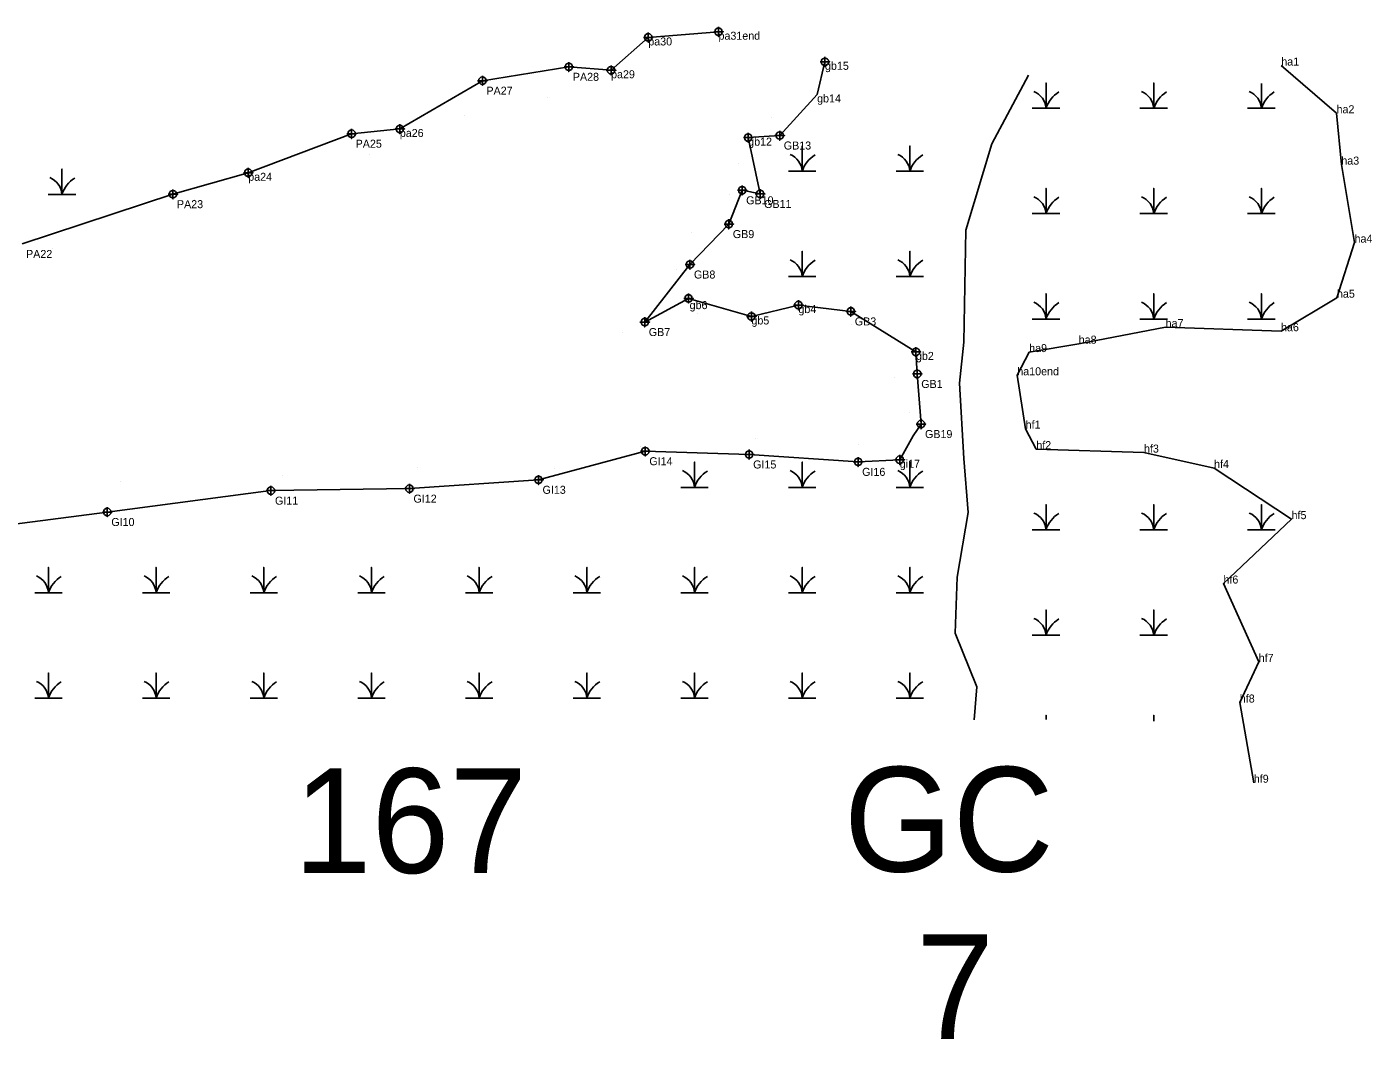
# Model space of a CAD drawing. Extents: x 2072529 to 2268796, y 436423 to 470397.
# Drawn here: x 2186918 to 2187758, y 453120 to 453752 of the extents above; entities that cross this region are included whole.
import ezdxf

# ---------------------------------------------------------------- set-up
doc = ezdxf.new("R2010")
doc.units = 0
for name, color, linetype in [('Default', 7, 'Continuous'), ('Exist Environmental Wetland Boundary', 7, 'Continuous'), ('Exist Environmental Wetland Boundary Cogo Comment', 7, 'Continuous'), ('Exist Environmental Wetland Boundary Cogo Point CELL', 7, 'Continuous'), ('Exist Hydro Jurisdictional Stream or Body of Water NEU Mitigable', 7, 'Continuous'), ('Exist Hydro Swamp or Marsh', 7, 'Continuous')]:
    doc.layers.add(name, color=color, linetype=linetype)

msp = doc.modelspace()

# ---------------------------------------------------------------- linework, layer by layer
at = {"layer": 'Exist Environmental Wetland Boundary'}
for points in [[(2186914.68, 453616.56), (2187008.89, 453647.61), (2187055.94, 453660.98), (2187120.52, 453685.38), (2187150.61, 453688.32), (2187202.21, 453718.49), (2187256.17, 453727.15), (2187282.56, 453725), (2187305.8, 453745.49), (2187349.64, 453749.06)], [(2187476.13, 453504.11), (2187473.78, 453535.38), (2187472.97, 453549.14), (2187432.29, 453574.42), (2187399.56, 453578.39), (2187370.22, 453571.28), (2187330.92, 453582.59), (2187303.63, 453567.79), (2187331.81, 453603.71), (2187356.1, 453628.96), (2187364.42, 453650.04), (2187375.61, 453647.76), (2187368.19, 453682.93), (2187387.95, 453684.27), (2187411.24, 453709.91), (2187416.15, 453730.28)], [(2187701.15, 453727.92), (2187735.66, 453698.15), (2187738.65, 453666.09), (2187746.9, 453617.39), (2187735.92, 453583), (2187700.97, 453562.06), (2187628.91, 453564.59), (2187574.63, 453554.29), (2187543.69, 453549.04), (2187536.26, 453534.55), (2187541.47, 453501.21)], [(2186590.17, 453193.44), (2186576.37, 453212.42), (2186571.99, 453259.45), (2186574.44, 453309.06), (2186581.86, 453375.55), (2186597.55, 453411.45), (2186689.52, 453421.44), (2186746.86, 453423.8), (2186843.7, 453432.98), (2186967.92, 453449.19), (2187070.14, 453462.52), (2187156.63, 453463.76), (2187237.25, 453469.29), (2187303.93, 453487.14), (2187368.79, 453485.11), (2187436.86, 453480.5), (2187462.85, 453481.82), (2187471.15, 453496.67), (2187476.13, 453504.11)], [(2187541.47, 453501.21), (2187548.15, 453488.43), (2187615.39, 453486.28), (2187659.17, 453476.66), (2187707.57, 453444.73), (2187665.02, 453404.52), (2187687.06, 453355.6), (2187675.24, 453330.23), (2187683.99, 453280.14)]]:
    msp.add_lwpolyline(points, dxfattribs=at)
at = {"layer": 'Exist Environmental Wetland Boundary Cogo Point CELL'}
for p, q in [((2187305.8, 453745.49), (2187305.8, 453745.49)), ((2187349.64, 453749.06), (2187349.64, 453749.06)), ((2187416.15, 453730.28), (2187416.15, 453730.28)), ((2187701.15, 453727.92), (2187701.15, 453727.92)), ((2187282.56, 453725), (2187282.56, 453725)), ((2187411.24, 453709.91), (2187411.24, 453709.91)), ((2187242.75, 453708.29), (2187242.75, 453708.29)), ((2187190.78, 453696.74), (2187190.78, 453696.74)), ((2187382.85, 453695.75), (2187382.85, 453695.75)), ((2187735.66, 453698.15), (2187735.66, 453698.15)), ((2187150.61, 453688.32), (2187150.61, 453688.32)), ((2187368.19, 453682.93), (2187368.19, 453682.93)), ((2187131.67, 453672.34), (2187131.67, 453672.34)), ((2187055.94, 453660.98), (2187055.94, 453660.98)), ((2187362.14, 453666.49), (2187362.14, 453666.49)), ((2187738.65, 453666.09), (2187738.65, 453666.09)), ((2187022.2, 453644.42), (2187022.2, 453644.42)), ((2187356.65, 453647.29), (2187356.65, 453647.29)), ((2187332.48, 453623.94), (2187332.48, 453623.94)), ((2187746.9, 453617.39), (2187746.9, 453617.39)), ((2186933.88, 453613.88), (2186933.88, 453613.88)), ((2187323.38, 453600.64), (2187323.38, 453600.64)), ((2187399.56, 453578.39), (2187399.56, 453578.39)), ((2187735.92, 453583), (2187735.92, 453583)), ((2187336.61, 453573.27), (2187336.61, 453573.27)), ((2187370.22, 453571.28), (2187370.22, 453571.28)), ((2187289.47, 453561.32), (2187289.47, 453561.32)), ((2187432.56, 453566.23), (2187432.56, 453566.23)), ((2187628.91, 453564.59), (2187628.91, 453564.59)), ((2187700.97, 453562.06), (2187700.97, 453562.06)), ((2187574.63, 453554.29), (2187574.63, 453554.29)), ((2187472.97, 453549.14), (2187472.97, 453549.14)), ((2187543.69, 453549.04), (2187543.69, 453549.04)), ((2187536.26, 453534.55), (2187536.26, 453534.55)), ((2187459.49, 453533.03), (2187459.49, 453533.03)), ((2187468.82, 453511.58), (2187468.82, 453511.58)), ((2187541.47, 453501.21), (2187541.47, 453501.21)), ((2187372.89, 453494.83), (2187372.89, 453494.83)), ((2187471.15, 453496.67), (2187471.15, 453496.67)), ((2187471.15, 453496.67), (2187471.15, 453496.67)), ((2187301.03, 453490.02), (2187301.03, 453490.02)), ((2187437.13, 453491.21), (2187437.13, 453491.21)), ((2187548.15, 453488.43), (2187548.15, 453488.43)), ((2187615.39, 453486.28), (2187615.39, 453486.28)), ((2187161.36, 453477.08), (2187161.36, 453477.08)), ((2187247.26, 453476.05), (2187247.26, 453476.05)), ((2187462.85, 453481.82), (2187462.85, 453481.82)), ((2187659.17, 453476.66), (2187659.17, 453476.66)), ((2186976.12, 453468.4), (2186976.12, 453468.4)), ((2187077.3, 453472.28), (2187077.3, 453472.28)), ((2187707.57, 453444.73), (2187707.57, 453444.73)), ((2187665.02, 453404.52), (2187665.02, 453404.52)), ((2187687.06, 453355.6), (2187687.06, 453355.6)), ((2187675.24, 453330.23), (2187675.24, 453330.23)), ((2187683.99, 453280.14), (2187683.99, 453280.14))]:
    msp.add_line(p, q, dxfattribs=at)
for points in [[(2187349.64, 453752.06), (2187349.64, 453746.06), (2187349.64, 453749.06), (2187352.64, 453749.06), (2187346.64, 453749.06)], [(2187305.8, 453748.49), (2187305.8, 453742.49), (2187305.8, 453745.49), (2187308.8, 453745.49), (2187302.8, 453745.49)], [(2187256.17, 453730.15), (2187256.17, 453724.15), (2187256.17, 453727.15), (2187259.17, 453727.15), (2187253.17, 453727.15)], [(2187282.56, 453728), (2187282.56, 453722), (2187282.56, 453725), (2187285.56, 453725), (2187279.56, 453725)], [(2187416.15, 453733.28), (2187416.15, 453727.28), (2187416.15, 453730.28), (2187419.15, 453730.28), (2187413.15, 453730.28)], [(2187202.21, 453721.49), (2187202.21, 453715.49), (2187202.21, 453718.49), (2187205.21, 453718.49), (2187199.21, 453718.49)], [(2187120.52, 453688.38), (2187120.52, 453682.38), (2187120.52, 453685.38), (2187123.52, 453685.38), (2187117.52, 453685.38)], [(2187150.61, 453691.32), (2187150.61, 453685.32), (2187150.61, 453688.32), (2187153.61, 453688.32), (2187147.61, 453688.32)], [(2187368.19, 453685.93), (2187368.19, 453679.93), (2187368.19, 453682.93), (2187371.19, 453682.93), (2187365.19, 453682.93)], [(2187387.92, 453687.25), (2187387.92, 453681.25), (2187387.92, 453684.25), (2187390.92, 453684.25), (2187384.92, 453684.25)], [(2187055.94, 453663.98), (2187055.94, 453657.98), (2187055.94, 453660.98), (2187058.94, 453660.98), (2187052.94, 453660.98)], [(2187364.43, 453653.05), (2187364.43, 453647.05), (2187364.43, 453650.05), (2187367.43, 453650.05), (2187361.43, 453650.05)], [(2187008.9, 453650.63), (2187008.9, 453644.63), (2187008.9, 453647.63), (2187011.9, 453647.63), (2187005.9, 453647.63)], [(2187375.61, 453650.76), (2187375.61, 453644.76), (2187375.61, 453647.76), (2187378.61, 453647.76), (2187372.61, 453647.76)], [(2187356.1, 453631.96), (2187356.1, 453625.96), (2187356.1, 453628.96), (2187359.1, 453628.96), (2187353.1, 453628.96)], [(2187331.81, 453606.71), (2187331.81, 453600.71), (2187331.81, 453603.71), (2187334.81, 453603.71), (2187328.81, 453603.71)], [(2187330.92, 453585.58), (2187330.92, 453579.58), (2187330.92, 453582.58), (2187333.92, 453582.58), (2187327.92, 453582.58)], [(2187399.56, 453581.39), (2187399.56, 453575.39), (2187399.56, 453578.39), (2187402.56, 453578.39), (2187396.56, 453578.39)], [(2187432.29, 453577.42), (2187432.29, 453571.42), (2187432.29, 453574.42), (2187435.29, 453574.42), (2187429.29, 453574.42)], [(2187303.62, 453570.79), (2187303.62, 453564.79), (2187303.62, 453567.79), (2187306.62, 453567.79), (2187300.62, 453567.79)], [(2187370.22, 453574.28), (2187370.22, 453568.28), (2187370.22, 453571.28), (2187373.22, 453571.28), (2187367.22, 453571.28)], [(2187472.98, 453552.11), (2187472.98, 453546.11), (2187472.98, 453549.11), (2187475.98, 453549.11), (2187469.98, 453549.11)], [(2187473.78, 453538.38), (2187473.78, 453532.38), (2187473.78, 453535.38), (2187476.78, 453535.38), (2187470.78, 453535.38)], [(2187476.13, 453507.11), (2187476.13, 453501.11), (2187476.13, 453504.11), (2187479.13, 453504.11), (2187473.13, 453504.11)], [(2187303.93, 453490.14), (2187303.93, 453484.14), (2187303.93, 453487.14), (2187306.93, 453487.14), (2187300.93, 453487.14)], [(2187368.79, 453488.11), (2187368.79, 453482.11), (2187368.79, 453485.11), (2187371.79, 453485.11), (2187365.79, 453485.11)], [(2187436.86, 453483.5), (2187436.86, 453477.5), (2187436.86, 453480.5), (2187439.86, 453480.5), (2187433.86, 453480.5)], [(2187462.85, 453484.82), (2187462.85, 453478.82), (2187462.85, 453481.82), (2187465.85, 453481.82), (2187459.85, 453481.82)], [(2187156.63, 453466.76), (2187156.63, 453460.76), (2187156.63, 453463.76), (2187159.63, 453463.76), (2187153.63, 453463.76)], [(2187237.25, 453472.29), (2187237.25, 453466.29), (2187237.25, 453469.29), (2187240.25, 453469.29), (2187234.25, 453469.29)], [(2187070.14, 453465.52), (2187070.14, 453459.52), (2187070.14, 453462.52), (2187073.14, 453462.52), (2187067.14, 453462.52)], [(2186967.92, 453452.19), (2186967.92, 453446.19), (2186967.92, 453449.19), (2186970.92, 453449.19), (2186964.92, 453449.19)]]:
    msp.add_lwpolyline(points, dxfattribs=at)
for centre in [(2187305.8, 453745.49), (2187349.64, 453749.06), (2187256.17, 453727.15), (2187282.56, 453725), (2187416.15, 453730.28), (2187202.21, 453718.49), (2187120.52, 453685.38), (2187150.61, 453688.32), (2187368.19, 453682.93), (2187387.92, 453684.25), (2187055.94, 453660.98), (2187364.43, 453650.05), (2187008.9, 453647.63), (2187375.61, 453647.76), (2187356.1, 453628.96), (2187331.81, 453603.71), (2187330.92, 453582.58), (2187399.56, 453578.39), (2187432.29, 453574.42), (2187303.62, 453567.79), (2187370.22, 453571.28), (2187472.98, 453549.11), (2187473.78, 453535.38), (2187476.13, 453504.11), (2187303.93, 453487.14), (2187368.79, 453485.11), (2187436.86, 453480.5), (2187462.85, 453481.82), (2187156.63, 453463.76), (2187237.25, 453469.29), (2187070.14, 453462.52), (2186967.92, 453449.19)]:
    msp.add_circle(centre, 2.34, dxfattribs=at)
at = {"layer": 'Exist Hydro Jurisdictional Stream or Body of Water NEU Mitigable'}
msp.add_lwpolyline([(2187543.28, 453721.89), (2187520.32, 453678.99), (2187504.18, 453625.18), (2187502.84, 453555.22), (2187500.15, 453529.65), (2187502.84, 453482.56), (2187505.53, 453448.93), (2187498.81, 453408.57), (2187497.46, 453373.59), (2187510.91, 453339.95), (2187509.43, 453319.33)], dxfattribs=at)
at = {"layer": 'Exist Hydro Swamp or Marsh'}
for points in [[(2187545.62, 453701.28), (2187554.22, 453701.28), (2187554.22, 453717.06), (2187554.22, 453701.28), (2187562.82, 453701.28)], [(2187612.87, 453701.28), (2187621.47, 453701.28), (2187621.47, 453717.06), (2187621.47, 453701.28), (2187630.07, 453701.28)], [(2187680.12, 453701.28), (2187688.72, 453701.28), (2187688.72, 453716.73)], [(2187688.72, 453716.73), (2187688.72, 453701.28), (2187697.32, 453701.28)], [(2187393.32, 453661.97), (2187401.92, 453661.97), (2187401.92, 453677.75), (2187401.92, 453661.97), (2187410.52, 453661.97)], [(2187460.57, 453661.97), (2187469.17, 453661.97), (2187469.17, 453677.75), (2187469.17, 453661.97), (2187477.77, 453661.97)], [(2186930.98, 453647.47), (2186939.58, 453647.47), (2186939.58, 453663.25), (2186939.58, 453647.47), (2186948.19, 453647.47)], [(2187545.62, 453635.48), (2187554.22, 453635.48), (2187554.22, 453651.26), (2187554.22, 453635.48), (2187562.82, 453635.48)], [(2187612.87, 453635.48), (2187621.47, 453635.48), (2187621.47, 453651.26), (2187621.47, 453635.48), (2187630.07, 453635.48)], [(2187680.12, 453635.48), (2187688.72, 453635.48), (2187688.72, 453651.26), (2187688.72, 453635.48), (2187697.32, 453635.48)], [(2187393.32, 453596.17), (2187401.92, 453596.17), (2187401.92, 453611.95), (2187401.92, 453596.17), (2187410.52, 453596.17)], [(2187460.57, 453596.17), (2187469.17, 453596.17), (2187469.17, 453611.95), (2187469.17, 453596.17), (2187477.77, 453596.17)], [(2187545.62, 453569.68), (2187554.22, 453569.68), (2187554.22, 453585.46), (2187554.22, 453569.68), (2187562.82, 453569.68)], [(2187612.87, 453569.68), (2187621.47, 453569.68), (2187621.47, 453585.46), (2187621.47, 453569.68), (2187630.07, 453569.68)], [(2187680.12, 453569.68), (2187688.72, 453569.68), (2187688.72, 453585.46), (2187688.72, 453569.68), (2187697.32, 453569.68)], [(2187326.07, 453464.57), (2187334.67, 453464.57), (2187334.67, 453480.35), (2187334.67, 453464.57), (2187343.27, 453464.57)], [(2187393.32, 453464.57), (2187401.92, 453464.57), (2187401.92, 453480.35), (2187401.92, 453464.57), (2187410.52, 453464.57)], [(2187460.57, 453464.57), (2187469.17, 453464.57), (2187469.17, 453480.35), (2187469.17, 453464.57), (2187477.77, 453464.57)], [(2187545.62, 453438.08), (2187554.22, 453438.08), (2187554.22, 453453.86), (2187554.22, 453438.08), (2187562.82, 453438.08)], [(2187612.87, 453438.08), (2187621.47, 453438.08), (2187621.47, 453453.86), (2187621.47, 453438.08), (2187630.07, 453438.08)], [(2187680.12, 453438.08), (2187688.72, 453438.08), (2187688.72, 453453.86), (2187688.72, 453438.08), (2187697.32, 453438.08)], [(2186922.57, 453398.77), (2186931.17, 453398.77), (2186931.17, 453414.55), (2186931.17, 453398.77), (2186939.77, 453398.77)], [(2186989.82, 453398.77), (2186998.42, 453398.77), (2186998.42, 453414.55), (2186998.42, 453398.77), (2187007.02, 453398.77)], [(2187057.07, 453398.77), (2187065.67, 453398.77), (2187065.67, 453414.55), (2187065.67, 453398.77), (2187074.27, 453398.77)], [(2187124.32, 453398.77), (2187132.92, 453398.77), (2187132.92, 453414.55), (2187132.92, 453398.77), (2187141.52, 453398.77)], [(2187191.57, 453398.77), (2187200.17, 453398.77), (2187200.17, 453414.55), (2187200.17, 453398.77), (2187208.77, 453398.77)], [(2187258.82, 453398.77), (2187267.42, 453398.77), (2187267.42, 453414.55), (2187267.42, 453398.77), (2187276.02, 453398.77)], [(2187326.07, 453398.77), (2187334.67, 453398.77), (2187334.67, 453414.55), (2187334.67, 453398.77), (2187343.27, 453398.77)], [(2187393.32, 453398.77), (2187401.92, 453398.77), (2187401.92, 453414.55), (2187401.92, 453398.77), (2187410.52, 453398.77)], [(2187460.57, 453398.77), (2187469.17, 453398.77), (2187469.17, 453414.55), (2187469.17, 453398.77), (2187477.77, 453398.77)], [(2187545.62, 453372.28), (2187554.22, 453372.28), (2187554.22, 453388.06), (2187554.22, 453372.28), (2187562.82, 453372.28)], [(2187612.87, 453372.28), (2187621.47, 453372.28), (2187621.47, 453388.06), (2187621.47, 453372.28), (2187630.07, 453372.28)], [(2186922.57, 453332.97), (2186931.17, 453332.97), (2186931.17, 453348.75), (2186931.17, 453332.97), (2186939.77, 453332.97)], [(2186989.82, 453332.97), (2186998.42, 453332.97), (2186998.42, 453348.75), (2186998.42, 453332.97), (2187007.02, 453332.97)], [(2187057.07, 453332.97), (2187065.67, 453332.97), (2187065.67, 453348.75), (2187065.67, 453332.97), (2187074.27, 453332.97)], [(2187124.32, 453332.97), (2187132.92, 453332.97), (2187132.92, 453348.75), (2187132.92, 453332.97), (2187141.52, 453332.97)], [(2187191.57, 453332.97), (2187200.17, 453332.97), (2187200.17, 453348.75), (2187200.17, 453332.97), (2187208.77, 453332.97)], [(2187258.82, 453332.97), (2187267.42, 453332.97), (2187267.42, 453348.75), (2187267.42, 453332.97), (2187276.02, 453332.97)], [(2187326.07, 453332.97), (2187334.67, 453332.97), (2187334.67, 453348.75), (2187334.67, 453332.97), (2187343.27, 453332.97)], [(2187393.32, 453332.97), (2187401.92, 453332.97), (2187401.92, 453348.75), (2187401.92, 453332.97), (2187410.52, 453332.97)], [(2187460.57, 453332.97), (2187469.17, 453332.97), (2187469.17, 453348.75), (2187469.17, 453332.97), (2187477.77, 453332.97)], [(2187554.22, 453319.7), (2187554.22, 453322.26), (2187554.22, 453319.7)], [(2187621.47, 453318.51), (2187621.47, 453322.26), (2187621.47, 453318.51)]]:
    msp.add_lwpolyline(points, dxfattribs=at)
for centre, radius, start, end in [((2187541.95, 453700.39), 12.3, 4.14034, 67.53497), ((2187572.46, 453695.22), 19.22, 122.12745, 161.62219), ((2187609.2, 453700.39), 12.3, 4.14034, 67.53497), ((2187639.71, 453695.22), 19.22, 122.12745, 161.62219), ((2187676.45, 453700.39), 12.3, 4.14034, 67.53497), ((2187706.96, 453695.22), 19.22, 122.12745, 161.62219), ((2187389.65, 453661.08), 12.3, 4.14034, 67.53497), ((2187420.16, 453655.91), 19.22, 122.12745, 161.62219), ((2187456.9, 453661.08), 12.3, 4.14034, 67.53497), ((2187487.41, 453655.91), 19.22, 122.12745, 161.62219), ((2186927.32, 453646.58), 12.3, 4.14034, 67.53497), ((2186957.83, 453641.41), 19.22, 122.12745, 161.62219), ((2187541.95, 453634.59), 12.3, 4.14034, 67.53497), ((2187572.46, 453629.42), 19.22, 122.12745, 161.62219), ((2187609.2, 453634.59), 12.3, 4.14034, 67.53497), ((2187639.71, 453629.42), 19.22, 122.12745, 161.62219), ((2187676.45, 453634.59), 12.3, 4.14034, 67.53497), ((2187706.96, 453629.42), 19.22, 122.12745, 161.62219), ((2187389.65, 453595.28), 12.3, 4.14034, 67.53497), ((2187420.16, 453590.11), 19.22, 122.12745, 161.62219), ((2187456.9, 453595.28), 12.3, 4.14034, 67.53497), ((2187487.41, 453590.11), 19.22, 122.12745, 161.62219), ((2187541.95, 453568.79), 12.3, 4.14034, 67.53497), ((2187572.46, 453563.62), 19.22, 122.12745, 161.62219), ((2187609.2, 453568.79), 12.3, 4.14034, 67.53497), ((2187639.71, 453563.62), 19.22, 122.12745, 161.62219), ((2187676.45, 453568.79), 12.3, 4.14034, 67.53497), ((2187706.96, 453563.62), 19.22, 122.12745, 161.62219), ((2187322.4, 453463.68), 12.3, 4.14034, 67.53497), ((2187352.91, 453458.51), 19.22, 122.12745, 161.62219), ((2187389.65, 453463.68), 12.3, 4.14034, 67.53497), ((2187420.16, 453458.51), 19.22, 122.12745, 161.62219), ((2187456.9, 453463.68), 12.3, 4.14034, 67.53497), ((2187487.41, 453458.51), 19.22, 122.12745, 161.62219), ((2187541.95, 453437.19), 12.3, 4.14034, 67.53497), ((2187572.46, 453432.02), 19.22, 122.12745, 161.62219), ((2187609.2, 453437.19), 12.3, 4.14034, 67.53497), ((2187639.71, 453432.02), 19.22, 122.12745, 161.62219), ((2187676.45, 453437.19), 12.3, 4.14034, 67.53497), ((2187706.96, 453432.02), 19.22, 122.12745, 161.62219), ((2186918.9, 453397.88), 12.3, 4.14034, 67.53497), ((2186949.41, 453392.71), 19.22, 122.12745, 161.62219), ((2186986.15, 453397.88), 12.3, 4.14034, 67.53497), ((2187016.66, 453392.71), 19.22, 122.12745, 161.62219), ((2187053.4, 453397.88), 12.3, 4.14034, 67.53497), ((2187083.91, 453392.71), 19.22, 122.12745, 161.62219), ((2187120.65, 453397.88), 12.3, 4.14034, 67.53497), ((2187151.16, 453392.71), 19.22, 122.12745, 161.62219), ((2187187.9, 453397.88), 12.3, 4.14034, 67.53497), ((2187218.41, 453392.71), 19.22, 122.12745, 161.62219), ((2187255.15, 453397.88), 12.3, 4.14034, 67.53497), ((2187285.66, 453392.71), 19.22, 122.12745, 161.62219), ((2187322.4, 453397.88), 12.3, 4.14034, 67.53497), ((2187352.91, 453392.71), 19.22, 122.12745, 161.62219), ((2187389.65, 453397.88), 12.3, 4.14034, 67.53497), ((2187420.16, 453392.71), 19.22, 122.12745, 161.62219), ((2187456.9, 453397.88), 12.3, 4.14034, 67.53497), ((2187487.41, 453392.71), 19.22, 122.12745, 161.62219), ((2187541.95, 453371.39), 12.3, 4.14034, 67.53497), ((2187572.46, 453366.22), 19.22, 122.12745, 161.62219), ((2187609.2, 453371.39), 12.3, 4.14034, 67.53497), ((2187639.71, 453366.22), 19.22, 122.12745, 161.62219), ((2186918.9, 453332.08), 12.3, 4.14034, 67.53497), ((2186949.41, 453326.91), 19.22, 122.12745, 161.62219), ((2186986.15, 453332.08), 12.3, 4.14034, 67.53497), ((2187016.66, 453326.91), 19.22, 122.12745, 161.62219), ((2187053.4, 453332.08), 12.3, 4.14034, 67.53497), ((2187083.91, 453326.91), 19.22, 122.12745, 161.62219), ((2187120.65, 453332.08), 12.3, 4.14034, 67.53497), ((2187151.16, 453326.91), 19.22, 122.12745, 161.62219), ((2187187.9, 453332.08), 12.3, 4.14034, 67.53497), ((2187218.41, 453326.91), 19.22, 122.12745, 161.62219), ((2187255.15, 453332.08), 12.3, 4.14034, 67.53497), ((2187285.66, 453326.91), 19.22, 122.12745, 161.62219), ((2187322.4, 453332.08), 12.3, 4.14034, 67.53497), ((2187352.91, 453326.91), 19.22, 122.12745, 161.62219), ((2187389.65, 453332.08), 12.3, 4.14034, 67.53497), ((2187420.16, 453326.91), 19.22, 122.12745, 161.62219), ((2187456.9, 453332.08), 12.3, 4.14034, 67.53497), ((2187487.41, 453326.91), 19.22, 122.12745, 161.62219)]:
    msp.add_arc(centre, radius, start, end, dxfattribs=at)

# ---------------------------------------------------------------- texts
at = {"layer": 'Default'}
for s, p in [('167', (2187084.36, 453223.8)), ('GC', (2187427.97, 453224.65)), ('7', (2187473.13, 453120.1))]:
    msp.add_text(s, height=65.34, dxfattribs=at).set_placement(p)
at = {"layer": 'Exist Environmental Wetland Boundary Cogo Comment'}
for s, p in [('pa30', (2187305.8, 453740.49)), ('pa31end', (2187349.64, 453744.06)), ('gb15', (2187416.15, 453725.28)), ('ha1', (2187701.15, 453727.92)), ('PA28', (2187258.67, 453718.4)), ('pa29', (2187282.56, 453720)), ('PA27', (2187204.71, 453709.74)), ('gb14', (2187411.24, 453704.91)), ('ha2', (2187735.66, 453698.15)), ('pa26', (2187150.61, 453683.32)), ('PA25', (2187123.02, 453676.63)), ('gb12', (2187368.19, 453677.93)), ('GB13', (2187390.42, 453675.5)), ('ha3', (2187738.65, 453666.09)), ('pa24', (2187055.94, 453655.98)), ('PA23', (2187011.4, 453638.88)), ('GB10', (2187366.93, 453641.3)), ('GB11', (2187378.11, 453639.01)), ('GB9', (2187358.6, 453620.21)), ('ha4', (2187746.9, 453617.39)), ('PA22', (2186917.18, 453607.81)), ('GB8', (2187334.31, 453594.96)), ('ha5', (2187735.92, 453583)), ('gb6', (2187331.61, 453575.85)), ('gb4', (2187399.56, 453573.39)), ('gb5', (2187370.22, 453566.28)), ('GB3', (2187434.79, 453565.67)), ('ha7', (2187628.91, 453564.59)), ('ha6', (2187700.97, 453562.06)), ('GB7', (2187306.12, 453559.04)), ('ha8', (2187574.63, 453554.29)), ('ha9', (2187543.69, 453549.04)), ('gb2', (2187472.97, 453544.14)), ('ha10end', (2187536.26, 453534.55)), ('GB1', (2187476.28, 453526.63)), ('GB19', (2187478.63, 453495.36)), ('hf1', (2187541.47, 453501.21)), ('hf2', (2187548.15, 453488.43)), ('hf3', (2187615.39, 453486.28)), ('GI14', (2187306.43, 453478.39)), ('GI15', (2187371.29, 453476.36)), ('GI16', (2187439.36, 453471.75)), ('gi17', (2187462.85, 453476.82)), ('hf4', (2187659.17, 453476.66)), ('GI11', (2187072.64, 453453.77)), ('GI12', (2187159.13, 453455.01)), ('GI13', (2187239.75, 453460.54)), ('hf5', (2187707.57, 453444.73)), ('GI10', (2186970.42, 453440.44)), ('hf6', (2187665.02, 453404.52)), ('hf7', (2187687.06, 453355.6)), ('hf8', (2187675.24, 453330.23)), ('hf9', (2187683.99, 453280.14))]:
    msp.add_text(s, height=5, dxfattribs=at).set_placement(p)

doc.saveas('drawing.dxf')
